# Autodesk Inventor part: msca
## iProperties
Shininess: 64.0
Length Units: 11269
Angle Units: 11279
Time Units: 11290
Mass Units: 11283
Length Display Precision: 3
Angle Display Precision: 2
Compacted: True
Part Number: msca
Document SubType Name: Modeling
Created: 2004-07
Designer: Peter
Manufacturer: Standard
Standards Organization: Custom
Density: 0.0
Volumn: 0.0
Area: 0.0
PropertySet Name: Model Information
Control State: 0
Master: False
Checked Out: False
Author: Peter
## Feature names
1. Extrusion2
